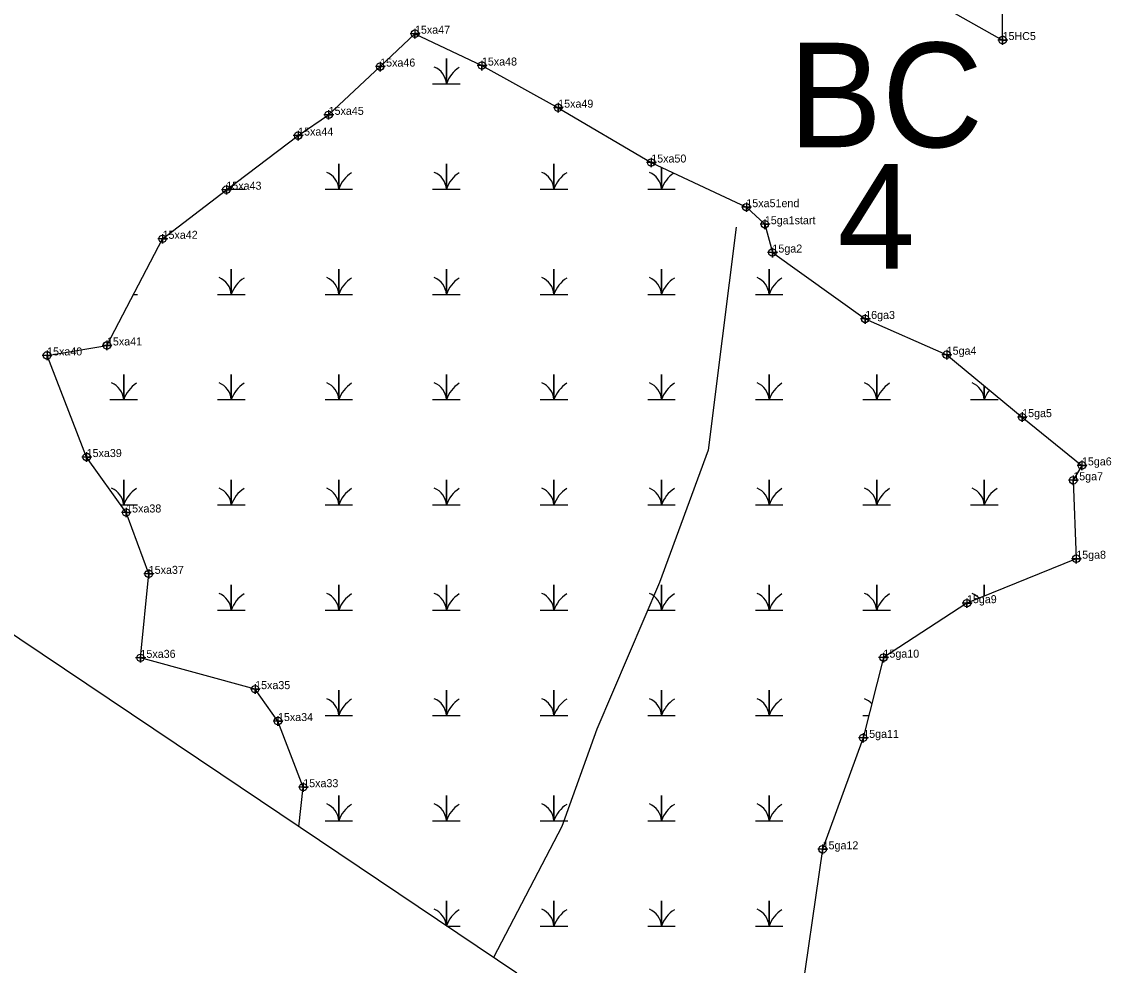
# Model space of a CAD drawing. Extents: x 2071991 to 2268989, y 436479 to 469629.
# Drawn here: x 2264685 to 2265365, y 444171 to 444761 of the extents above; entities that cross this region are included whole.
import ezdxf

# ---------------------------------------------------------------- set-up
doc = ezdxf.new("R2010")
doc.units = 0
for name, color, linetype in [('approx_PSA', 7, 'Continuous'), ('Default', 7, 'Continuous'), ('Exist Environmental Wetland Boundary', 7, 'Continuous'), ('Exist Environmental Wetland Boundary Cogo Comment', 7, 'Continuous'), ('Exist Environmental Wetland Boundary Cogo Point CELL', 7, 'Continuous'), ('Exist Hydro Jurisdictional Stream or Body of Water NEU Mitigable', 7, 'Continuous'), ('Exist Hydro Swamp or Marsh', 7, 'Continuous')]:
    doc.layers.add(name, color=color, linetype=linetype)

msp = doc.modelspace()

# ---------------------------------------------------------------- linework, layer by layer
at = {"layer": 'approx_PSA'}
for p, q in [((2264809.27, 444290.73), (2264188.42, 444707.74)), ((2264994.16, 444166.54), (2264809.27, 444290.73))]:
    msp.add_line(p, q, dxfattribs=at)
at = {"layer": 'Exist Environmental Wetland Boundary'}
for points in [[(2265261.4, 444769.86), (2265297.62, 444749.53), (2265297.63, 444766.39)], [(2264858, 444258), (2264860.73, 444282.69), (2264844.95, 444324.01), (2264830.7, 444343.96), (2264759.06, 444363.51), (2264764.23, 444415.99), (2264750.13, 444454.33), (2264725.44, 444488.97), (2264700.73, 444552.47), (2264738.11, 444558.71), (2264772.85, 444625.33), (2264812.71, 444656.03), (2264857.55, 444689.85), (2264876.61, 444702.8), (2264908.81, 444732.97), (2264930.55, 444753.51), (2264972.35, 444733.61), (2265020.01, 444707.27), (2265078.14, 444673.01), (2265137.56, 444645.11), (2265149.11, 444634.45)], [(2265149.11, 444634.45), (2265153.86, 444616.76), (2265211.81, 444575.26), (2265262.73, 444552.92), (2265309.87, 444513.92), (2265347.2, 444483.75), (2265341.79, 444474.46), (2265343.64, 444425.44), (2265275.37, 444397.67), (2265223.22, 444363.64), (2265210.56, 444313.51), (2265185.22, 444243.87), (2265169.99, 444139)]]:
    msp.add_lwpolyline(points, dxfattribs=at)
at = {"layer": 'Exist Environmental Wetland Boundary Cogo Point CELL'}
for points in [[(2264930.55, 444756.51), (2264930.55, 444750.51), (2264930.55, 444753.51), (2264933.55, 444753.51), (2264927.55, 444753.51)], [(2265297.62, 444752.53), (2265297.62, 444746.53), (2265297.62, 444749.53), (2265300.62, 444749.53), (2265294.62, 444749.53)], [(2264908.81, 444735.97), (2264908.81, 444729.97), (2264908.81, 444732.97), (2264911.81, 444732.97), (2264905.81, 444732.97)], [(2264972.35, 444736.61), (2264972.35, 444730.61), (2264972.35, 444733.61), (2264975.35, 444733.61), (2264969.35, 444733.61)], [(2265020.01, 444710.27), (2265020.01, 444704.27), (2265020.01, 444707.27), (2265023.01, 444707.27), (2265017.01, 444707.27)], [(2264876.61, 444705.8), (2264876.61, 444699.8), (2264876.61, 444702.8), (2264879.61, 444702.8), (2264873.61, 444702.8)], [(2264857.55, 444692.85), (2264857.55, 444686.85), (2264857.55, 444689.85), (2264860.55, 444689.85), (2264854.55, 444689.85)], [(2265078.14, 444676.01), (2265078.14, 444670.01), (2265078.14, 444673.01), (2265081.14, 444673.01), (2265075.14, 444673.01)], [(2264812.71, 444659.03), (2264812.71, 444653.03), (2264812.71, 444656.03), (2264815.71, 444656.03), (2264809.71, 444656.03)], [(2265137.56, 444648.11), (2265137.56, 444642.11), (2265137.56, 444645.11), (2265140.56, 444645.11), (2265134.56, 444645.11)], [(2265149.11, 444637.45), (2265149.11, 444631.45), (2265149.11, 444634.45), (2265152.11, 444634.45), (2265146.11, 444634.45)], [(2264772.85, 444628.33), (2264772.85, 444622.33), (2264772.85, 444625.33), (2264775.85, 444625.33), (2264769.85, 444625.33)], [(2265153.86, 444619.76), (2265153.86, 444613.76), (2265153.86, 444616.76), (2265156.86, 444616.76), (2265150.86, 444616.76)], [(2265211.81, 444578.26), (2265211.81, 444572.26), (2265211.81, 444575.26), (2265214.81, 444575.26), (2265208.81, 444575.26)], [(2264738.11, 444561.71), (2264738.11, 444555.71), (2264738.11, 444558.71), (2264741.11, 444558.71), (2264735.11, 444558.71)], [(2264700.73, 444555.47), (2264700.73, 444549.47), (2264700.73, 444552.47), (2264703.73, 444552.47), (2264697.73, 444552.47)], [(2265262.73, 444555.92), (2265262.73, 444549.92), (2265262.73, 444552.92), (2265265.73, 444552.92), (2265259.73, 444552.92)], [(2265309.87, 444516.92), (2265309.87, 444510.92), (2265309.87, 444513.92), (2265312.87, 444513.92), (2265306.87, 444513.92)], [(2264725.44, 444491.97), (2264725.44, 444485.97), (2264725.44, 444488.97), (2264728.44, 444488.97), (2264722.44, 444488.97)], [(2265347.2, 444486.75), (2265347.2, 444480.75), (2265347.2, 444483.75), (2265350.2, 444483.75), (2265344.2, 444483.75)], [(2265341.79, 444477.46), (2265341.79, 444471.46), (2265341.79, 444474.46), (2265344.79, 444474.46), (2265338.79, 444474.46)], [(2264750.13, 444457.33), (2264750.13, 444451.33), (2264750.13, 444454.33), (2264753.13, 444454.33), (2264747.13, 444454.33)], [(2265343.64, 444428.44), (2265343.64, 444422.44), (2265343.64, 444425.44), (2265346.64, 444425.44), (2265340.64, 444425.44)], [(2264764.23, 444418.99), (2264764.23, 444412.99), (2264764.23, 444415.99), (2264767.23, 444415.99), (2264761.23, 444415.99)], [(2265275.37, 444400.67), (2265275.37, 444394.67), (2265275.37, 444397.67), (2265278.37, 444397.67), (2265272.37, 444397.67)], [(2264759.06, 444366.51), (2264759.06, 444360.51), (2264759.06, 444363.51), (2264762.06, 444363.51), (2264756.06, 444363.51)], [(2265223.22, 444366.64), (2265223.22, 444360.64), (2265223.22, 444363.64), (2265226.22, 444363.64), (2265220.22, 444363.64)], [(2264830.7, 444346.96), (2264830.7, 444340.96), (2264830.7, 444343.96), (2264833.7, 444343.96), (2264827.7, 444343.96)], [(2264844.95, 444327.01), (2264844.95, 444321.01), (2264844.95, 444324.01), (2264847.95, 444324.01), (2264841.95, 444324.01)], [(2265210.56, 444316.51), (2265210.56, 444310.51), (2265210.56, 444313.51), (2265213.56, 444313.51), (2265207.56, 444313.51)], [(2264860.73, 444285.69), (2264860.73, 444279.69), (2264860.73, 444282.69), (2264863.73, 444282.69), (2264857.73, 444282.69)], [(2265185.22, 444246.87), (2265185.22, 444240.87), (2265185.22, 444243.87), (2265188.22, 444243.87), (2265182.22, 444243.87)]]:
    msp.add_lwpolyline(points, dxfattribs=at)
for centre in [(2264930.55, 444753.51), (2265297.62, 444749.53), (2264908.81, 444732.97), (2264972.35, 444733.61), (2265020.01, 444707.27), (2264876.61, 444702.8), (2264857.55, 444689.85), (2265078.14, 444673.01), (2264812.71, 444656.03), (2265137.56, 444645.11), (2265149.11, 444634.45), (2264772.85, 444625.33), (2265153.86, 444616.76), (2265211.81, 444575.26), (2264738.11, 444558.71), (2264700.73, 444552.47), (2265262.73, 444552.92), (2265309.87, 444513.92), (2264725.44, 444488.97), (2265347.2, 444483.75), (2265341.79, 444474.46), (2264750.13, 444454.33), (2265343.64, 444425.44), (2264764.23, 444415.99), (2265275.37, 444397.67), (2264759.06, 444363.51), (2265223.22, 444363.64), (2264830.7, 444343.96), (2264844.95, 444324.01), (2265210.56, 444313.51), (2264860.73, 444282.69), (2265185.22, 444243.87)]:
    msp.add_circle(centre, 2.34, dxfattribs=at)
at = {"layer": 'Exist Hydro Jurisdictional Stream or Body of Water NEU Mitigable'}
msp.add_lwpolyline([(2265131.15, 444632.65), (2265122.45, 444562.95), (2265113.74, 444493.26), (2265083.27, 444410.5), (2265044.1, 444319.03), (2265022.33, 444258.05), (2264979.56, 444176.35)], dxfattribs=at)
at = {"layer": 'Exist Hydro Swamp or Marsh'}
for p, q in [((2264754.75, 444590.61), (2264757.17, 444590.61)), ((2265210.39, 444327.49), (2265214.09, 444327.49)), ((2264950.41, 444195.93), (2264958.78, 444195.93))]:
    msp.add_line(p, q, dxfattribs=at)
for points in [[(2264941.58, 444722.18), (2264950.18, 444722.18), (2264950.18, 444737.96), (2264950.18, 444722.18), (2264958.78, 444722.18)], [(2264874.37, 444656.4), (2264882.98, 444656.4), (2264882.98, 444672.18), (2264882.98, 444656.4), (2264891.58, 444656.4)], [(2264941.58, 444656.4), (2264950.18, 444656.4), (2264950.18, 444672.18), (2264950.18, 444656.4), (2264958.78, 444656.4)], [(2265008.78, 444656.4), (2265017.38, 444656.4), (2265017.38, 444672.18), (2265017.38, 444656.4), (2265025.98, 444656.4)], [(2265075.98, 444656.4), (2265084.59, 444656.4), (2265084.59, 444669.98)], [(2265084.59, 444669.98), (2265084.59, 444656.4), (2265093.19, 444656.4)], [(2264813.2, 444656.4), (2264815.77, 444656.4), (2264815.77, 444658.34)], [(2264815.77, 444658.34), (2264815.77, 444656.4), (2264824.37, 444656.4)], [(2264807.17, 444590.61), (2264815.77, 444590.61), (2264815.77, 444606.4), (2264815.77, 444590.61), (2264824.37, 444590.61)], [(2264874.37, 444590.61), (2264882.98, 444590.61), (2264882.98, 444606.4), (2264882.98, 444590.61), (2264891.58, 444590.61)], [(2264941.58, 444590.61), (2264950.18, 444590.61), (2264950.18, 444606.4), (2264950.18, 444590.61), (2264958.78, 444590.61)], [(2265008.78, 444590.61), (2265017.38, 444590.61), (2265017.38, 444606.4), (2265017.38, 444590.61), (2265025.98, 444590.61)], [(2265075.98, 444590.61), (2265084.59, 444590.61), (2265084.59, 444606.4), (2265084.59, 444590.61), (2265093.19, 444590.61)], [(2265143.19, 444590.61), (2265151.79, 444590.61), (2265151.79, 444606.4), (2265151.79, 444590.61), (2265160.39, 444590.61)], [(2264739.97, 444524.83), (2264748.57, 444524.83), (2264748.57, 444540.61), (2264748.57, 444524.83), (2264757.17, 444524.83)], [(2264807.17, 444524.83), (2264815.77, 444524.83), (2264815.77, 444540.61), (2264815.77, 444524.83), (2264824.37, 444524.83)], [(2264874.37, 444524.83), (2264882.98, 444524.83), (2264882.98, 444540.61), (2264882.98, 444524.83), (2264891.58, 444524.83)], [(2264941.58, 444524.83), (2264950.18, 444524.83), (2264950.18, 444540.61), (2264950.18, 444524.83), (2264958.78, 444524.83)], [(2265008.78, 444524.83), (2265017.38, 444524.83), (2265017.38, 444540.61), (2265017.38, 444524.83), (2265025.98, 444524.83)], [(2265075.98, 444524.83), (2265084.59, 444524.83), (2265084.59, 444540.61), (2265084.59, 444524.83), (2265093.19, 444524.83)], [(2265143.19, 444524.83), (2265151.79, 444524.83), (2265151.79, 444540.61), (2265151.79, 444524.83), (2265160.39, 444524.83)], [(2265210.39, 444524.83), (2265218.99, 444524.83), (2265218.99, 444540.61), (2265218.99, 444524.83), (2265227.59, 444524.83)], [(2265277.59, 444524.83), (2265286.2, 444524.83), (2265286.2, 444533.5)], [(2265286.2, 444533.5), (2265286.2, 444524.83), (2265294.8, 444524.83)], [(2264746.77, 444459.05), (2264748.57, 444459.05), (2264748.57, 444474.83), (2264748.57, 444459.05), (2264757.17, 444459.05)], [(2264807.17, 444459.05), (2264815.77, 444459.05), (2264815.77, 444474.83), (2264815.77, 444459.05), (2264824.37, 444459.05)], [(2264874.37, 444459.05), (2264882.98, 444459.05), (2264882.98, 444474.83), (2264882.98, 444459.05), (2264891.58, 444459.05)], [(2264941.58, 444459.05), (2264950.18, 444459.05), (2264950.18, 444474.83), (2264950.18, 444459.05), (2264958.78, 444459.05)], [(2265008.78, 444459.05), (2265017.38, 444459.05), (2265017.38, 444474.83), (2265017.38, 444459.05), (2265025.98, 444459.05)], [(2265075.98, 444459.05), (2265084.59, 444459.05), (2265084.59, 444474.83), (2265084.59, 444459.05), (2265093.19, 444459.05)], [(2265143.19, 444459.05), (2265151.79, 444459.05), (2265151.79, 444474.83), (2265151.79, 444459.05), (2265160.39, 444459.05)], [(2265210.39, 444459.05), (2265218.99, 444459.05), (2265218.99, 444474.83), (2265218.99, 444459.05), (2265227.59, 444459.05)], [(2265277.59, 444459.05), (2265286.2, 444459.05), (2265286.2, 444474.83), (2265286.2, 444459.05), (2265294.8, 444459.05)], [(2264807.17, 444393.27), (2264815.77, 444393.27), (2264815.77, 444409.05), (2264815.77, 444393.27), (2264824.37, 444393.27)], [(2264874.37, 444393.27), (2264882.98, 444393.27), (2264882.98, 444409.05), (2264882.98, 444393.27), (2264891.58, 444393.27)], [(2264941.58, 444393.27), (2264950.18, 444393.27), (2264950.18, 444409.05), (2264950.18, 444393.27), (2264958.78, 444393.27)], [(2265008.78, 444393.27), (2265017.38, 444393.27), (2265017.38, 444409.05), (2265017.38, 444393.27), (2265025.98, 444393.27)], [(2265075.98, 444393.27), (2265084.59, 444393.27), (2265084.59, 444409.05), (2265084.59, 444393.27), (2265093.19, 444393.27)], [(2265143.19, 444393.27), (2265151.79, 444393.27), (2265151.79, 444409.05), (2265151.79, 444393.27), (2265160.39, 444393.27)], [(2265210.39, 444393.27), (2265218.99, 444393.27), (2265218.99, 444409.05), (2265218.99, 444393.27), (2265227.59, 444393.27)], [(2265286.2, 444402.08), (2265286.2, 444409.05), (2265286.2, 444402.08)], [(2264874.37, 444327.49), (2264882.98, 444327.49), (2264882.98, 444343.27), (2264882.98, 444327.49), (2264891.58, 444327.49)], [(2264941.58, 444327.49), (2264950.18, 444327.49), (2264950.18, 444343.27), (2264950.18, 444327.49), (2264958.78, 444327.49)], [(2265008.78, 444327.49), (2265017.38, 444327.49), (2265017.38, 444343.27), (2265017.38, 444327.49), (2265025.98, 444327.49)], [(2265075.98, 444327.49), (2265084.59, 444327.49), (2265084.59, 444343.27), (2265084.59, 444327.49), (2265093.19, 444327.49)], [(2265143.19, 444327.49), (2265151.79, 444327.49), (2265151.79, 444343.27), (2265151.79, 444327.49), (2265160.39, 444327.49)], [(2264874.37, 444261.71), (2264882.98, 444261.71), (2264882.98, 444277.49), (2264882.98, 444261.71), (2264891.58, 444261.71)], [(2264941.58, 444261.71), (2264950.18, 444261.71), (2264950.18, 444277.49), (2264950.18, 444261.71), (2264958.78, 444261.71)], [(2265008.78, 444261.71), (2265017.38, 444261.71), (2265017.38, 444277.49), (2265017.38, 444261.71), (2265025.98, 444261.71)], [(2265075.98, 444261.71), (2265084.59, 444261.71), (2265084.59, 444277.49), (2265084.59, 444261.71), (2265093.19, 444261.71)], [(2265143.19, 444261.71), (2265151.79, 444261.71), (2265151.79, 444277.49), (2265151.79, 444261.71), (2265160.39, 444261.71)], [(2264950.18, 444196.08), (2264950.18, 444211.71), (2264950.18, 444196.08)], [(2265008.78, 444195.93), (2265017.38, 444195.93), (2265017.38, 444211.71), (2265017.38, 444195.93), (2265025.98, 444195.93)], [(2265075.98, 444195.93), (2265084.59, 444195.93), (2265084.59, 444211.71), (2265084.59, 444195.93), (2265093.19, 444195.93)], [(2265143.19, 444195.93), (2265151.79, 444195.93), (2265151.79, 444211.71), (2265151.79, 444195.93), (2265160.39, 444195.93)]]:
    msp.add_lwpolyline(points, dxfattribs=at)
for centre, radius, start, end in [((2264937.91, 444721.29), 12.3, 4.14034, 67.53497), ((2264968.42, 444716.12), 19.22, 122.12745, 161.62219), ((2264870.71, 444655.51), 12.3, 4.14034, 67.53497), ((2264901.22, 444650.33), 19.22, 122.12745, 161.62219), ((2264937.91, 444655.51), 12.3, 4.14034, 67.53497), ((2264968.42, 444650.33), 19.22, 122.12745, 161.62219), ((2265005.12, 444655.51), 12.3, 4.14034, 67.53497), ((2265035.62, 444650.33), 19.22, 122.12745, 161.62219), ((2265072.32, 444655.51), 12.3, 4.14034, 67.53497), ((2265102.83, 444650.33), 19.22, 123.38823, 161.62219), ((2264803.51, 444655.51), 12.3, 4.14034, 12.38824), ((2264834.01, 444650.33), 19.22, 152.35814, 161.62219), ((2264803.51, 444589.73), 12.3, 4.14034, 67.53497), ((2264834.01, 444584.55), 19.22, 122.12745, 161.62219), ((2264870.71, 444589.73), 12.3, 4.14034, 67.53497), ((2264901.22, 444584.55), 19.22, 122.12745, 161.62219), ((2264937.91, 444589.73), 12.3, 4.14034, 67.53497), ((2264968.42, 444584.55), 19.22, 122.12745, 161.62219), ((2265005.12, 444589.73), 12.3, 4.14034, 67.53497), ((2265035.62, 444584.55), 19.22, 122.12745, 161.62219), ((2265072.32, 444589.73), 12.3, 4.14034, 67.53497), ((2265102.83, 444584.55), 19.22, 122.12745, 161.62219), ((2265139.52, 444589.73), 12.3, 4.14034, 67.53497), ((2265170.03, 444584.55), 19.22, 122.12745, 161.62219), ((2264736.3, 444523.95), 12.3, 4.14034, 67.53497), ((2264766.81, 444518.77), 19.22, 122.12745, 161.62219), ((2264803.51, 444523.95), 12.3, 4.14034, 67.53497), ((2264834.01, 444518.77), 19.22, 122.12745, 161.62219), ((2264870.71, 444523.95), 12.3, 4.14034, 67.53497), ((2264901.22, 444518.77), 19.22, 122.12745, 161.62219), ((2264937.91, 444523.95), 12.3, 4.14034, 67.53497), ((2264968.42, 444518.77), 19.22, 122.12745, 161.62219), ((2265005.12, 444523.95), 12.3, 4.14034, 67.53497), ((2265035.62, 444518.77), 19.22, 122.12745, 161.62219), ((2265072.32, 444523.95), 12.3, 4.14034, 67.53497), ((2265102.83, 444518.77), 19.22, 122.12745, 161.62219), ((2265139.52, 444523.95), 12.3, 4.14034, 67.53497), ((2265170.03, 444518.77), 19.22, 122.12745, 161.62219), ((2265206.73, 444523.95), 12.3, 4.14034, 67.53497), ((2265237.23, 444518.77), 19.22, 122.12745, 161.62219), ((2265273.93, 444523.95), 12.3, 4.14034, 67.53497), ((2265304.44, 444518.77), 19.22, 141.23037, 161.62219), ((2264736.3, 444458.17), 12.3, 4.14034, 67.53497), ((2264766.81, 444452.99), 19.22, 122.12745, 161.62219), ((2264803.51, 444458.17), 12.3, 4.14034, 67.53497), ((2264834.01, 444452.99), 19.22, 122.12745, 161.62219), ((2264870.71, 444458.17), 12.3, 4.14034, 67.53497), ((2264901.22, 444452.99), 19.22, 122.12745, 161.62219), ((2264937.91, 444458.17), 12.3, 4.14034, 67.53497), ((2264968.42, 444452.99), 19.22, 122.12745, 161.62219), ((2265005.12, 444458.17), 12.3, 4.14034, 67.53497), ((2265035.62, 444452.99), 19.22, 122.12745, 161.62219), ((2265072.32, 444458.17), 12.3, 4.14034, 67.53497), ((2265102.83, 444452.99), 19.22, 122.12745, 161.62219), ((2265139.52, 444458.17), 12.3, 4.14034, 67.53497), ((2265170.03, 444452.99), 19.22, 122.12745, 161.62219), ((2265206.73, 444458.17), 12.3, 4.14034, 67.53497), ((2265237.23, 444452.99), 19.22, 122.12745, 161.62219), ((2265273.93, 444458.17), 12.3, 4.14034, 67.53497), ((2265304.44, 444452.99), 19.22, 122.12745, 161.62219), ((2264803.51, 444392.39), 12.3, 4.14034, 67.53497), ((2264834.01, 444387.21), 19.22, 122.12745, 161.62219), ((2264870.71, 444392.39), 12.3, 4.14034, 67.53497), ((2264901.22, 444387.21), 19.22, 122.12745, 161.62219), ((2264937.91, 444392.39), 12.3, 4.14034, 67.53497), ((2264968.42, 444387.21), 19.22, 122.12745, 161.62219), ((2265005.12, 444392.39), 12.3, 4.14034, 67.53497), ((2265035.62, 444387.21), 19.22, 122.12745, 161.62219), ((2265072.32, 444392.39), 12.3, 4.14034, 67.53497), ((2265102.83, 444387.21), 19.22, 122.12745, 161.62219), ((2265139.52, 444392.39), 12.3, 4.14034, 67.53497), ((2265170.03, 444387.21), 19.22, 122.12745, 161.62219), ((2265206.73, 444392.39), 12.3, 4.14034, 67.53497), ((2265237.23, 444387.21), 19.22, 122.12745, 161.62219), ((2265273.93, 444392.39), 12.3, 42.87911, 67.53497), ((2264870.71, 444326.6), 12.3, 4.14034, 67.53497), ((2264901.22, 444321.43), 19.22, 122.12745, 161.62219), ((2264937.91, 444326.6), 12.3, 4.14034, 67.53497), ((2264968.42, 444321.43), 19.22, 122.12745, 161.62219), ((2265005.12, 444326.6), 12.3, 4.14034, 67.53497), ((2265035.62, 444321.43), 19.22, 122.12745, 161.62219), ((2265072.32, 444326.6), 12.3, 4.14034, 67.53497), ((2265102.83, 444321.43), 19.22, 122.12745, 161.62219), ((2265139.52, 444326.6), 12.3, 4.14034, 67.53497), ((2265170.03, 444321.43), 19.22, 122.12745, 161.62219), ((2265206.73, 444326.6), 12.3, 41.55694, 67.53497), ((2264870.71, 444260.82), 12.3, 4.14034, 67.53497), ((2264901.22, 444255.65), 19.22, 122.12745, 161.62219), ((2264937.91, 444260.82), 12.3, 4.14034, 67.53497), ((2264968.42, 444255.65), 19.22, 122.12745, 161.62219), ((2265005.12, 444260.82), 12.3, 4.14034, 67.53497), ((2265035.62, 444255.65), 19.22, 122.12745, 161.62219), ((2265072.32, 444260.82), 12.3, 4.14034, 67.53497), ((2265102.83, 444255.65), 19.22, 122.12745, 161.62219), ((2265139.52, 444260.82), 12.3, 4.14034, 67.53497), ((2265170.03, 444255.65), 19.22, 122.12745, 161.62219), ((2264937.91, 444195.04), 12.3, 4.89007, 67.53497), ((2264968.42, 444189.87), 19.22, 122.12745, 161.23245), ((2265005.12, 444195.04), 12.3, 4.14034, 67.53497), ((2265035.62, 444189.87), 19.22, 122.12745, 161.62219), ((2265072.32, 444195.04), 12.3, 4.14034, 67.53497), ((2265102.83, 444189.87), 19.22, 122.12745, 161.62219), ((2265139.52, 444195.04), 12.3, 4.14034, 67.53497), ((2265170.03, 444189.87), 19.22, 122.12745, 161.62219)]:
    msp.add_arc(centre, radius, start, end, dxfattribs=at)

# ---------------------------------------------------------------- texts
at = {"layer": 'Default'}
for s, p in [('BC', (2265164.01, 444682.57)), ('4', (2265194.49, 444606.76))]:
    msp.add_text(s, height=65.34, dxfattribs=at).set_placement(p)
at = {"layer": 'Exist Environmental Wetland Boundary Cogo Comment'}
for s, p in [('15xa47', (2264930.55, 444753.51)), ('15HC5', (2265297.62, 444749.53)), ('15xa46', (2264908.81, 444732.97)), ('15xa48', (2264972.35, 444733.61)), ('15xa49', (2265020.01, 444707.27)), ('15xa45', (2264876.61, 444702.8)), ('15xa44', (2264857.55, 444689.85)), ('15xa50', (2265078.14, 444673.01)), ('15xa43', (2264812.71, 444656.03)), ('15xa51end', (2265137.56, 444645.11)), ('15ga1start', (2265149.11, 444634.45)), ('15xa42', (2264772.85, 444625.33)), ('15ga2', (2265153.86, 444616.76)), ('16ga3', (2265211.81, 444575.26)), ('15xa41', (2264738.11, 444558.71)), ('15xa40', (2264700.73, 444552.47)), ('15ga4', (2265262.73, 444552.92)), ('15ga5', (2265309.87, 444513.92)), ('15xa39', (2264725.44, 444488.97)), ('15ga6', (2265347.2, 444483.75)), ('15ga7', (2265341.79, 444474.46)), ('15xa38', (2264750.13, 444454.33)), ('15ga8', (2265343.64, 444425.44)), ('15xa37', (2264764.23, 444415.99)), ('15ga9', (2265275.37, 444397.67)), ('15xa36', (2264759.06, 444363.51)), ('15ga10', (2265223.22, 444363.64)), ('15xa35', (2264830.7, 444343.96)), ('15xa34', (2264844.95, 444324.01)), ('15ga11', (2265210.56, 444313.51)), ('15xa33', (2264860.73, 444282.69)), ('15ga12', (2265185.22, 444243.87))]:
    msp.add_text(s, height=5, dxfattribs=at).set_placement(p)

doc.saveas('drawing.dxf')
